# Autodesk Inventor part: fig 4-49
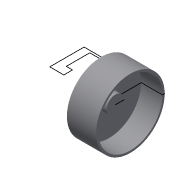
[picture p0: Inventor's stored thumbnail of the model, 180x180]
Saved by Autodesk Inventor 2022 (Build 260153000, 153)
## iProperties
Created: 2004-05
Part Number: fig 4-49
Document SubType Name: Modeling
Designer: CADCIM Technologies
Manufacturer: Standard
Standards Organization: Custom
Density: 1 g/cm^3
Material: Generic
Appearance: Default
Author: CADCIM Technologies
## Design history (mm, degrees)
sketch "Sketch1"
  geometry: L1 (37.08, 12.209)-(23.643, 12.209); L2 (23.643, 12.209)-(23.643, 45.026); L3 (23.643, 45.026)-(51.55, 45.026); L4 (51.55, 45.026)-(51.55, 42.959); L5 (51.55, 42.959)-(31.137, 42.959); L6 (31.137, 42.959)-(31.137, 20.478); L7 (31.137, 20.478)-(37.08, 20.478); L8 (37.08, 20.478)-(37.08, 12.209); L9 (86.437, 12.209)-(73, 12.209); L10 (73, 12.209)-(73, 45.026); L11 (73, 45.026)-(100.907, 45.026); L12 (100.907, 45.026)-(100.907, 42.959); L13 (100.907, 42.959)-(80.494, 42.959); L14 (80.494, 42.959)-(80.494, 20.478); L15 (80.494, 20.478)-(86.437, 20.478); L16 (86.437, 20.478)-(86.437, 12.209)
  constraints: 32 end point, 12 parallel, 2 horizontal, 2 perpendicular
revolve "Revolution1" sketch "Sketch1" stored, may be unused: angle "d0" = 90 deg
body "Solid1"
